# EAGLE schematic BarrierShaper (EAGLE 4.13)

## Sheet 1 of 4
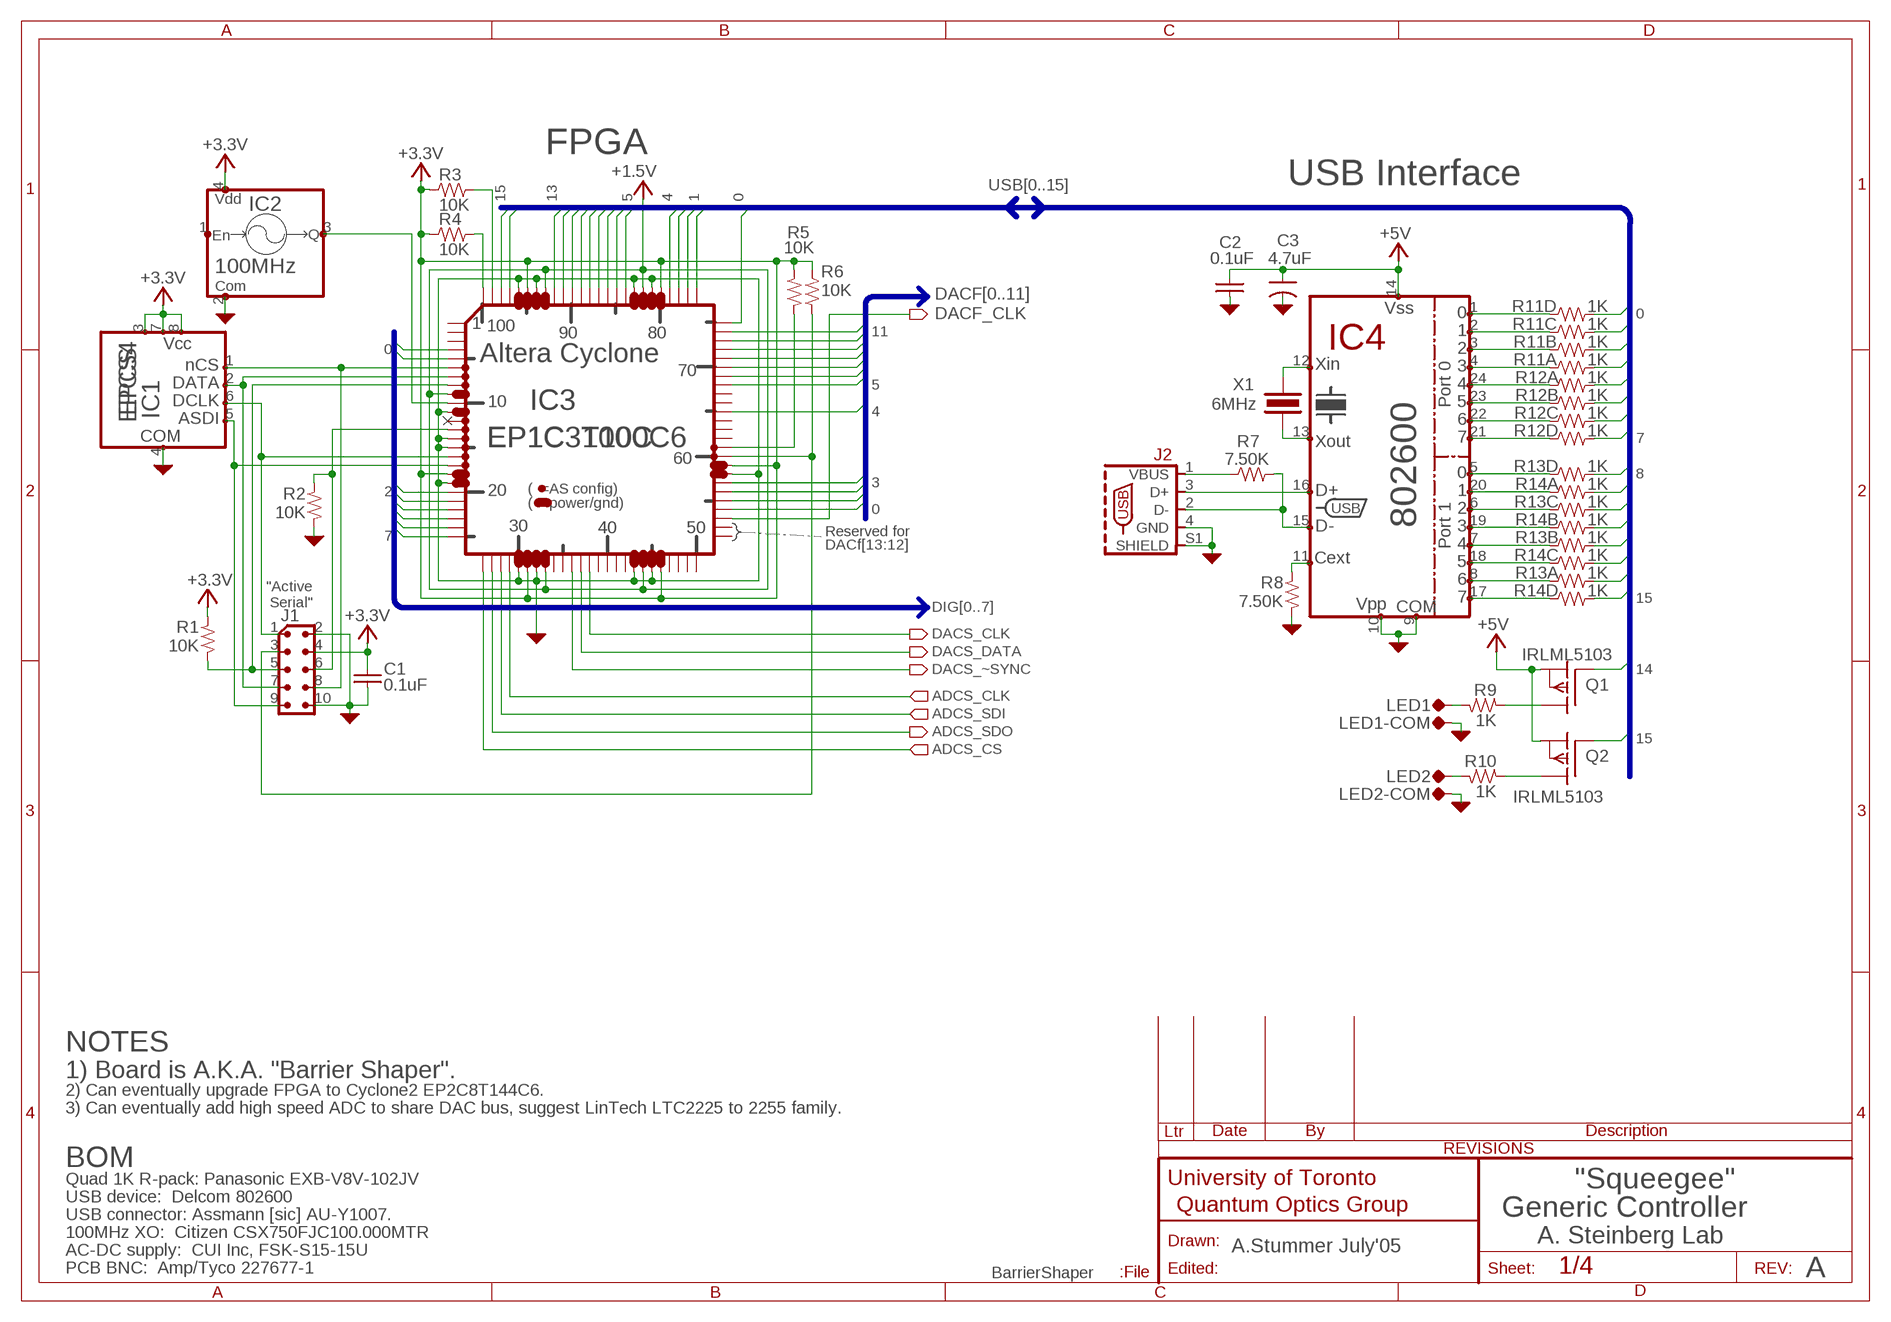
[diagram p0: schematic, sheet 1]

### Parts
C1  0.1uF  CAP-V-0805  [0805]
C2  0.1uF  CAP-V-0603  [0603]
C3  4.7uF  CAP-POL-3216  [EIA3216]
IC1  EPCS4  EPCS1-4(ALTERA_CONFIG)  [SOIC-8]
IC2  100MHz  CSX750(CITIZEN_OSC)  [CSX750(CITIZEN_OSC)]
IC3  EP1C3T100C6  ALTERA_EP1C--100--TQFP100  [TQFP-100]
IC4  802600(DELCOM-USB)-SOIC24  [SOIC-24-0.3]
J1  CONN-2X5-BLASTER  [CONN-2X5-BLASTER]
J2  AU-Y1007-USB-B  [CONN-USB_AU-Y1007]
LED1  TP-HOLE-0.042  [TP-HOLE]
LED1-COM  TP-HOLE-0.042  [TP-HOLE]
LED2  TP-HOLE-0.042  [TP-HOLE]
LED2-COM  TP-HOLE-0.042  [TP-HOLE]
Q1  IRLML5103  MOSFET-P-SOT23  [SOT23]
Q2  IRLML5103  MOSFET-P-SOT23  [SOT23]
R1  10K  R-V-0805  [0805]
R2  10K  R-V-0805  [0805]
R3  10K  R-H-0805  [0805]
R4  10K  R-H-0805  [0805]
R5  10K  R-V-0805  [0805]
R6  10K  R-V-0805  [0805]
R7  7.50K  R-H-0805  [0805]
R8  7.50K  R-V-0805  [0805]
R9  1K  R-H-0805  [0805]
R10  1K  R-H-0805  [0805]
R11  1K  R-4PAK-EXB-8V8  [PANASONIC_EXB-V8V(QUAD-R-PACK)]
R12  1K  R-4PAK-EXB-8V8  [PANASONIC_EXB-V8V(QUAD-R-PACK)]
R13  1K  R-4PAK-EXB-8V8  [PANASONIC_EXB-V8V(QUAD-R-PACK)]
R14  1K  R-4PAK-EXB-8V8  [PANASONIC_EXB-V8V(QUAD-R-PACK)]
X1  6MHz  XTAL/RESONATOR-P  [RESONATOR-P]

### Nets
+1.5V [Power]: IC3.9 IC3.33 IC3.44 IC3.82 IC3.93 ; also sheet 3
+3.3V [Power]: C1.2 IC1.3(VCC1) IC1.7(VCC2) IC1.8(VCC3) IC2.4(VDD) IC3.18 IC3.31 IC3.46 IC3.59 IC3.80 IC3.95 J1.4 R1.2 R3.1 R4.1 R5.2 R6.2 ; also sheet 2,3
+5V: C2.2 C3.+(POS) IC4.14(VCC) Q1.2(S) Q2.2(S) ; also sheet 2,3
ADCS_CLK: IC3.29 ; also sheet 2
ADCS_CS: IC3.26 ; also sheet 2
ADCS_SDI: IC3.28 ; also sheet 2
ADCS_SDO: IC3.27 ; also sheet 2
AGND: C1.1 C2.1 C3.-(NEG) IC1.4(COM) IC2.2(COM) IC3.11 IC3.14 IC3.15 IC3.19 IC3.30 IC3.32 IC3.43 IC3.45 IC3.58 IC3.81 IC3.83 IC3.94 IC3.96 IC4.9(COM) IC4.10(VPP) J1.2 J1.10 J2.4(GND) J2.S1(SHIELD) LED1-COM.P$1(TP) LED2-COM.P$1(TP) R2.1 R8.1 ; also sheet 2,3
DACF0: IC3.54 ; also sheet 2
DACF1: IC3.55 ; also sheet 2
DACF2: IC3.56 ; also sheet 2
DACF3: IC3.57 ; also sheet 2
DACF4: IC3.65 ; also sheet 2
DACF5: IC3.68 ; also sheet 2
DACF6: IC3.69 ; also sheet 2
DACF7: IC3.70 ; also sheet 2
DACF8: IC3.71 ; also sheet 2
DACF9: IC3.72 ; also sheet 2
DACF10: IC3.73 ; also sheet 2
DACF11: IC3.74 ; also sheet 2
DACF_CLK: IC3.53 ; also sheet 2
DACS_CLK: IC3.38 ; also sheet 2
DACS_DATA: IC3.37 ; also sheet 2
DACS_~SYNC: IC3.36 ; also sheet 2
DIG0: IC3.4 ; also sheet 2
DIG1: IC3.5 ; also sheet 2
DIG2: IC3.20 ; also sheet 2
DIG3: IC3.21 ; also sheet 2
DIG4: IC3.22 ; also sheet 2
DIG5: IC3.23 ; also sheet 2
DIG6: IC3.24 ; also sheet 2
DIG7: IC3.25 ; also sheet 2
N$1: IC1.1(NCS) IC3.6 J1.8
N$2: IC1.2(DATA) IC3.7 J1.7
N$3: IC1.6(DCLK) IC3.16 J1.1
N$4: IC1.5(ASDI) IC3.17 J1.9
N$5: IC3.60 J1.3 R6.1
N$6: IC3.8 J1.5 R1.1
N$7: IC3.13 J1.6 R2.2
N$8: IC3.61 R5.1
N$9: IC2.3(Q) IC3.10
N$10: IC3.100 R4.2
N$11: IC3.99 R3.2
N$62: IC4.8(P1.6) R13.1A
N$63: IC4.7(P1.4) R13.2A
N$64: IC4.17(P1.7) R14.4A
N$65: IC4.6(P1.2) R13.3A
N$66: IC4.19(P1.3) R14.2A
N$67: IC4.18(P1.5) R14.3A
N$68: IC4.20(P1.1) R14.1A
N$69: IC4.5(P1.0) R13.4A
N$70: IC4.15(D-) J2.2(D-) R7.2
N$71: IC4.16(D+) J2.3(D+)
N$72: IC4.13(XTL2) X1.1(X1)
N$73: IC4.12(XTL1) X1.2(X2)
N$74: Q1.3(D) R9.1
N$75: LED1.P$1(TP) R9.2
N$76: Q2.3(D) R10.1
N$77: LED2.P$1(TP) R10.2
N$78: IC4.11(CEXT) R8.2
N$79: IC4.4(P0.3) R11.1A
N$80: IC4.3(P0.2) R11.2A
N$81: IC4.21(P0.7) R12.4A
N$82: IC4.22(P0.6) R12.3A
N$83: IC4.23(P0.5) R12.2A
N$84: IC4.24(P0.4) R12.1A
N$85: IC4.2(P0.1) R11.3A
N$86: IC4.1(P0.0) R11.4A
N$104: J2.1(VBUS) R7.1
USB0: IC3.75 R11.4B
USB1: IC3.76 R11.3B
USB2: IC3.77 R11.2B
USB3: IC3.78 R11.1B
USB4: IC3.79 R12.1B
USB5: IC3.84 R12.2B
USB6: IC3.85 R12.3B
USB7: IC3.86 R12.4B
USB8: IC3.87 R13.4B
USB9: IC3.88 R14.1B
USB10: IC3.89 R13.3B
USB11: IC3.90 R14.2B
USB12: IC3.91 R13.2B
USB13: IC3.92 R14.3B
USB14: IC3.97 Q1.1(G) R13.1B
USB15: IC3.98 Q2.1(G) R14.4B
Unconnected: IC2.1(EN) IC3.1 IC3.2 IC3.3 IC3.12 IC3.34 IC3.35 IC3.39 IC3.40 IC3.41 IC3.42 IC3.47 IC3.48 IC3.49 IC3.50 IC3.51 IC3.52 IC3.62 IC3.63 IC3.64 IC3.66 IC3.67

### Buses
DACF[0..11]
USB[0..15]
DIG[0..7]

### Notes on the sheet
- FPGA
- USB Interface
- 15 | 13 | 5 | 4 | 1 | 0
- 0
- 11
- 0
- 5
- 4
- 7
- 8
- 3
- 2
- 0
- Reserved for
- 7
- DACf[13:12]
- "Active
- 15
- Serial"
- 14
- 15
- NOTES
- 1) Board is A.K.A. "Barrier Shaper".
- 2) Can eventually upgrade FPGA to Cyclone2 EP2C8T144C6.
- 3) Can eventually add high speed ADC to share DAC bus, suggest LinTech LTC2225 to 2255 family.
- BOM
- Quad 1K R-pack: Panasonic EXB-V8V-102JV | "Squeegee"
- USB device:  Delcom 802600
- USB connector: Assmann [sic] AU-Y1007. | Generic Controller
- 100MHz XO:  Citizen CSX750FJC100.000MTR
- A. Steinberg Lab
- AC-DC supply:  CUI Inc, FSK-S15-15U | A.Stummer July'05
- PCB BNC:  Amp/Tyco 227677-1 | A

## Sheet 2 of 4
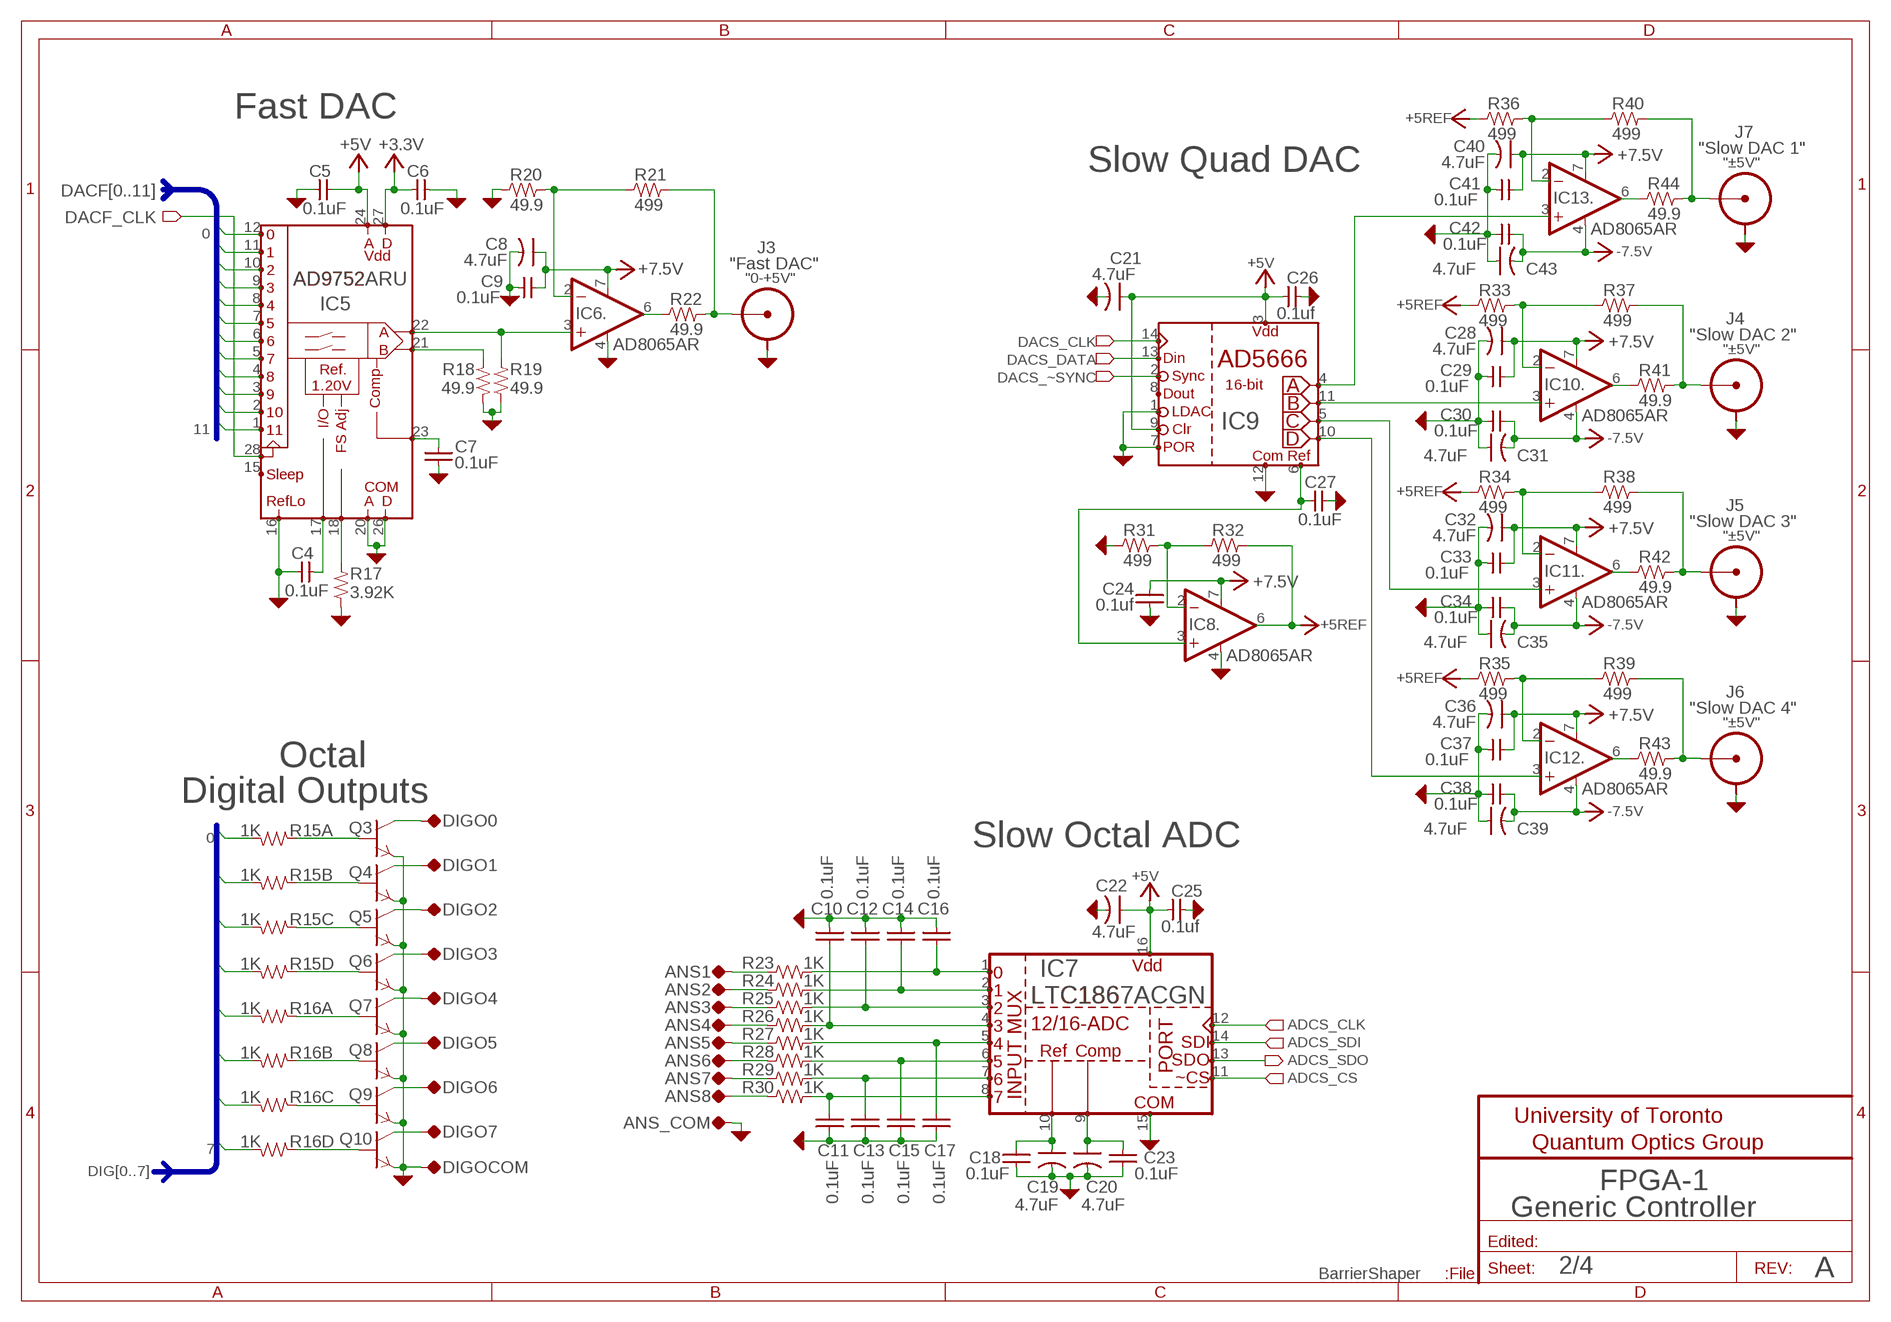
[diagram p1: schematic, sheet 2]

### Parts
ANS1  TP-0.042"  [TP-0.042]
ANS2  TP-0.042"  [TP-0.042]
ANS3  TP-0.042"  [TP-0.042]
ANS4  TP-0.042"  [TP-0.042]
ANS5  TP-0.042"  [TP-0.042]
ANS6  TP-0.042"  [TP-0.042]
ANS7  TP-0.042"  [TP-0.042]
ANS8  TP-0.042"  [TP-0.042]
ANS_COM  TP-0.042"  [TP-0.042]
C4  0.1uF  CAP-H-0805  [0805]
C5  0.1uF  CAP-H-0805  [0805]
C6  0.1uF  CAP-H-0805  [0805]
C7  0.1uF  CAP-V-0805  [0805]
C8  4.7uF  CAP-POL-3216  [EIA3216]
C9  0.1uF  CAP-H-0805  [0805]
C10  0.1uF  CAP-V-0805  [0805]
C11  0.1uF  CAP-V-0805  [0805]
C12  0.1uF  CAP-V-0805  [0805]
C13  0.1uF  CAP-V-0805  [0805]
C14  0.1uF  CAP-V-0805  [0805]
C15  0.1uF  CAP-V-0805  [0805]
C16  0.1uF  CAP-V-0805  [0805]
C17  0.1uF  CAP-V-0805  [0805]
C18  0.1uF  CAP-V-0603  [0603]
C19  4.7uF  CAP-POL-3216  [EIA3216]
C20  4.7uF  CAP-POL-3216  [EIA3216]
C21  4.7uF  CAP-POL-3216  [EIA3216]
C22  4.7uF  CAP-POL-3216  [EIA3216]
C23  0.1uF  CAP-V-0603  [0603]
C24  0.1uf  CAP-V-0603  [0603]
C25  0.1uf  CAP-H-0603  [0603]
C26  0.1uf  CAP-H-0603  [0603]
C27  0.1uF  CAP-H-0603  [0603]
C28  4.7uF  CAP-POL-3216  [EIA3216]
C29  0.1uF  CAP-H-0805  [0805]
C30  0.1uF  CAP-H-0805  [0805]
C31  4.7uF  CAP-POL-3216  [EIA3216]
C32  4.7uF  CAP-POL-3216  [EIA3216]
C33  0.1uF  CAP-H-0805  [0805]
C34  0.1uF  CAP-H-0805  [0805]
C35  4.7uF  CAP-POL-3216  [EIA3216]
C36  4.7uF  CAP-POL-3216  [EIA3216]
C37  0.1uF  CAP-H-0805  [0805]
C38  0.1uF  CAP-H-0805  [0805]
C39  4.7uF  CAP-POL-3216  [EIA3216]
C40  4.7uF  CAP-POL-3216  [EIA3216]
C41  0.1uF  CAP-H-0805  [0805]
C42  0.1uF  CAP-H-0805  [0805]
C43  4.7uF  CAP-POL-3216  [EIA3216]
DIGO0  TP-0.042"  [TP-0.042]
DIGO1  TP-0.042"  [TP-0.042]
DIGO2  TP-0.042"  [TP-0.042]
DIGO3  TP-0.042"  [TP-0.042]
DIGO4  TP-0.042"  [TP-0.042]
DIGO5  TP-0.042"  [TP-0.042]
DIGO6  TP-0.042"  [TP-0.042]
DIGO7  TP-0.042"  [TP-0.042]
DIGOCOM  TP-0.042"  [TP-0.042]
IC5  AD9752ARU  [TSSOP-28]
IC6  AD8065AR  OPAMP-SO8  [SOIC-8]
IC7  LTC1867ACGN  LTC1867(OCTAL12-16-ADC)  [SSOP-16]
IC8  AD8065AR  OPAMP-SO8  [SOIC-8]
IC9  AD5666(QUAD16-DAC)  [TSSOP-14]
IC10  AD8065AR  OPAMP-SO8  [SOIC-8]
IC11  AD8065AR  OPAMP-SO8  [SOIC-8]
IC12  AD8065AR  OPAMP-SO8  [SOIC-8]
IC13  AD8065AR  OPAMP-SO8  [SOIC-8]
J3  "Fast DAC"  CONN-BNCTYPE3HORIZ  [CONN-BNC-AMP-TYPE3HORIZ]
J4  "Slow DAC 2"  CONN-BNCTYPE3HORIZ  [CONN-BNC-AMP-TYPE3HORIZ]
J5  "Slow DAC 3"  CONN-BNCTYPE3HORIZ  [CONN-BNC-AMP-TYPE3HORIZ]
J6  "Slow DAC 4"  CONN-BNCTYPE3HORIZ  [CONN-BNC-AMP-TYPE3HORIZ]
J7  "Slow DAC 1"  CONN-BNCTYPE3HORIZ  [CONN-BNC-AMP-TYPE3HORIZ]
Q3  ZXT13N50DE6(ZETEX-NPN-SW-SOT223-6)  [SOT23-6MODIFIED]
Q4  ZXT13N50DE6(ZETEX-NPN-SW-SOT223-6)  [SOT23-6MODIFIED]
Q5  ZXT13N50DE6(ZETEX-NPN-SW-SOT223-6)  [SOT23-6MODIFIED]
Q6  ZXT13N50DE6(ZETEX-NPN-SW-SOT223-6)  [SOT23-6MODIFIED]
Q7  ZXT13N50DE6(ZETEX-NPN-SW-SOT223-6)  [SOT23-6MODIFIED]
Q8  ZXT13N50DE6(ZETEX-NPN-SW-SOT223-6)  [SOT23-6MODIFIED]
Q9  ZXT13N50DE6(ZETEX-NPN-SW-SOT223-6)  [SOT23-6MODIFIED]
Q10  ZXT13N50DE6(ZETEX-NPN-SW-SOT223-6)  [SOT23-6MODIFIED]
R15  1K  R-4PAK-EXB-8V8  [PANASONIC_EXB-V8V(QUAD-R-PACK)]
R16  1K  R-4PAK-EXB-8V8  [PANASONIC_EXB-V8V(QUAD-R-PACK)]
R17  3.92K  R-V-0805  [0805]
R18  49.9  R-V-0805  [0805]
R19  49.9  R-V-0805  [0805]
R20  49.9  R-H-0805  [0805]
R21  499  R-H-0805  [0805]
R22  49.9  R-H-0805  [0805]
R23  1K  R-H-0805  [0805]
R24  1K  R-H-0805  [0805]
R25  1K  R-H-0805  [0805]
R26  1K  R-H-0805  [0805]
R27  1K  R-H-0805  [0805]
R28  1K  R-H-0805  [0805]
R29  1K  R-H-0805  [0805]
R30  1K  R-H-0805  [0805]
R31  499  R-H-0805  [0805]
R32  499  R-H-0805  [0805]
R33  499  R-H-0805  [0805]
R34  499  R-H-0805  [0805]
R35  499  R-H-0805  [0805]
R36  499  R-H-0805  [0805]
R37  499  R-H-0805  [0805]
R38  499  R-H-0805  [0805]
R39  499  R-H-0805  [0805]
R40  499  R-H-0805  [0805]
R41  49.9  R-H-0805  [0805]
R42  49.9  R-H-0805  [0805]
R43  49.9  R-H-0805  [0805]
R44  49.9  R-H-0805  [0805]

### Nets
+3.3V [Power]: C6.1 IC5.27(DVDD) ; also sheet 1,3
+5REF: IC8.6(.:OUT) R32.2 R33.1 R34.1 R35.1 R36.1
+5V: C5.2 C21.+(POS) C22.+(POS) C25.1 C26.1 IC5.24(AVDD) IC7.16(VDD) IC9.3(VDD) IC9.9(~CLR) ; also sheet 1,3
+7.5V: C8.+(POS) C9.1 C24.2 C28.+(POS) C29.1 C32.+(POS) C33.1 C36.+(POS) C37.1 C40.+(POS) C41.1 IC6.7(V+) IC8.7(V+) IC10.7(V+) IC11.7(V+) IC12.7(V+) IC13.7(V+) ; also sheet 3
-7.5V: C30.1 C31.-(NEG) C34.1 C35.-(NEG) C38.1 C39.-(NEG) C42.1 C43.-(NEG) IC10.4(V-) IC11.4(V-) IC12.4(V-) IC13.4(V-) ; also sheet 3
ADCS_CLK: IC7.12(CLK) ; also sheet 1
ADCS_CS: IC7.11(~CS) ; also sheet 1
ADCS_SDI: IC7.14(SDI) ; also sheet 1
ADCS_SDO: IC7.13(SDO) ; also sheet 1
AGND: ANS_COM.TP C4.1 C5.1 C6.2 C7.1 C8.-(NEG) C9.2 C10.1 C11.1 C12.1 C13.1 C14.1 C15.1 C16.1 C17.1 C18.1 C19.-(NEG) C20.-(NEG) C21.-(NEG) C22.-(NEG) C23.1 C24.1 C25.2 C26.2 C27.2 C28.-(NEG) C29.2 C30.2 C31.+(POS) C32.-(NEG) C33.2 C34.2 C35.+(POS) C36.-(NEG) C37.2 C38.2 C39.+(POS) C40.-(NEG) C41.2 C42.2 C43.+(POS) DIGOCOM.TP IC5.16(REFLO) IC5.20(ACOM) IC5.26(DCOM) IC6.4(V-) IC7.15(COM) IC8.4(V-) IC9.1(~LDAC) IC9.7(POR) IC9.12(COM) J3.SHIELD J4.SHIELD J5.SHIELD J6.SHIELD J7.SHIELD Q3.4(E) Q4.4(E) Q5.4(E) Q6.4(E) Q7.4(E) Q8.4(E) Q9.4(E) Q10.4(E) R17.1 R18.1 R19.1 R20.1 R31.1 ; also sheet 1,3
DACF0: IC5.12 ; also sheet 1
DACF1: IC5.11 ; also sheet 1
DACF2: IC5.10 ; also sheet 1
DACF3: IC5.9 ; also sheet 1
DACF4: IC5.8 ; also sheet 1
DACF5: IC5.7 ; also sheet 1
DACF6: IC5.6 ; also sheet 1
DACF7: IC5.5 ; also sheet 1
DACF8: IC5.4 ; also sheet 1
DACF9: IC5.3 ; also sheet 1
DACF10: IC5.2 ; also sheet 1
DACF11: IC5.1 ; also sheet 1
DACF_CLK: IC5.28(CLK) ; also sheet 1
DACS_CLK: IC9.14(SCLK) ; also sheet 1
DACS_DATA: IC9.13(DIN) ; also sheet 1
DACS_~SYNC: IC9.2(~SYNC) ; also sheet 1
DIG0: R15.1B ; also sheet 1
DIG1: R15.2B ; also sheet 1
DIG2: R15.3B ; also sheet 1
DIG3: R15.4B ; also sheet 1
DIG4: R16.1B ; also sheet 1
DIG5: R16.2B ; also sheet 1
DIG6: R16.3B ; also sheet 1
DIG7: R16.4B ; also sheet 1
N$12: IC10.2(.:-IN) R33.2 R37.1
N$13: IC13.2(.:-IN) R36.2 R40.1
N$14: IC13.6(.:OUT) R44.1
N$15: J7.CONDUCTOR R40.2 R44.2
N$16: IC10.6(.:OUT) R41.1
N$17: C27.1 IC8.3(.:+IN) IC9.6(VREF)
N$18: J4.CONDUCTOR R37.2 R41.2
N$19: IC9.5(OUT-C) IC11.3(.:+IN)
N$20: DIGO6.TP Q9.1(C)
N$21: IC11.2(.:-IN) R34.2 R38.1
N$22: IC11.6(.:OUT) R42.1
N$23: J5.CONDUCTOR R38.2 R42.2
N$24: IC9.10(OUT-D) IC12.3(.:+IN)
N$25: IC12.2(.:-IN) R35.2 R39.1
N$26: IC12.6(.:OUT) R43.1
N$27: J6.CONDUCTOR R39.2 R43.2
N$28: C4.2 IC5.17(REF)
N$29: IC5.18(FSADJ) R17.2
N$30: IC5.21(IOUTB) R18.2
N$31: IC5.22(IOUTA) IC6.3(.:+IN) R19.2
N$32: C7.2 IC5.23(COMP)
N$33: IC6.2(.:-IN) R20.2 R21.1
N$34: IC6.6(.:OUT) R22.1
N$35: J3.CONDUCTOR R21.2 R22.2
N$36: IC9.11(OUT-B) IC10.3(.:+IN)
N$37: IC8.2(.:-IN) R31.2 R32.1
N$38: ANS1.TP R23.1
N$39: C18.2 C19.+(POS) IC7.10(VREF)
N$40: C20.+(POS) C23.2 IC7.9(COMP)
N$41: IC9.4(OUT-A) IC13.3(.:+IN)
N$42: C11.2 IC7.8 R30.2
N$43: C13.2 IC7.7 R29.2
N$44: C15.2 IC7.6 R28.2
N$45: C17.2 IC7.5 R27.2
N$46: C10.2 IC7.4 R26.2
N$47: C12.2 IC7.3 R25.2
N$48: C14.2 IC7.2 R24.2
N$49: C16.2 IC7.1 R23.2
N$50: ANS2.TP R24.1
N$51: ANS3.TP R25.1
N$52: ANS4.TP R26.1
N$53: ANS5.TP R27.1
N$54: ANS6.TP R28.1
N$55: ANS7.TP R29.1
N$56: ANS8.TP R30.1
N$57: DIGO7.TP Q10.1(C)
N$58: DIGO0.TP Q3.1(C)
N$59: DIGO1.TP Q4.1(C)
N$60: DIGO2.TP Q5.1(C)
N$61: DIGO3.TP Q6.1(C)
N$87: DIGO4.TP Q7.1(C)
N$88: DIGO5.TP Q8.1(C)
N$89: Q3.3(B) R15.1A
N$90: Q4.3(B) R15.2A
N$91: Q10.3(B) R16.4A
N$92: Q9.3(B) R16.3A
N$93: Q8.3(B) R16.2A
N$94: Q7.3(B) R16.1A
N$95: Q6.3(B) R15.4A
N$96: Q5.3(B) R15.3A
Unconnected: IC5.15(SLEEP) IC9.8(SDO)

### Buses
USB[0..15]
DACF[0..11]
DIG[0..7]

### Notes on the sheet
- Fast DAC
- "±5V"
- Slow Quad DAC
- 0
- "0-+5V"
- "±5V"
- 11
- "±5V"
- "±5V"
- Octal
- Digital Outputs
- 0
- Slow Octal ADC
- 7
- FPGA-1
- Generic Controller
- A

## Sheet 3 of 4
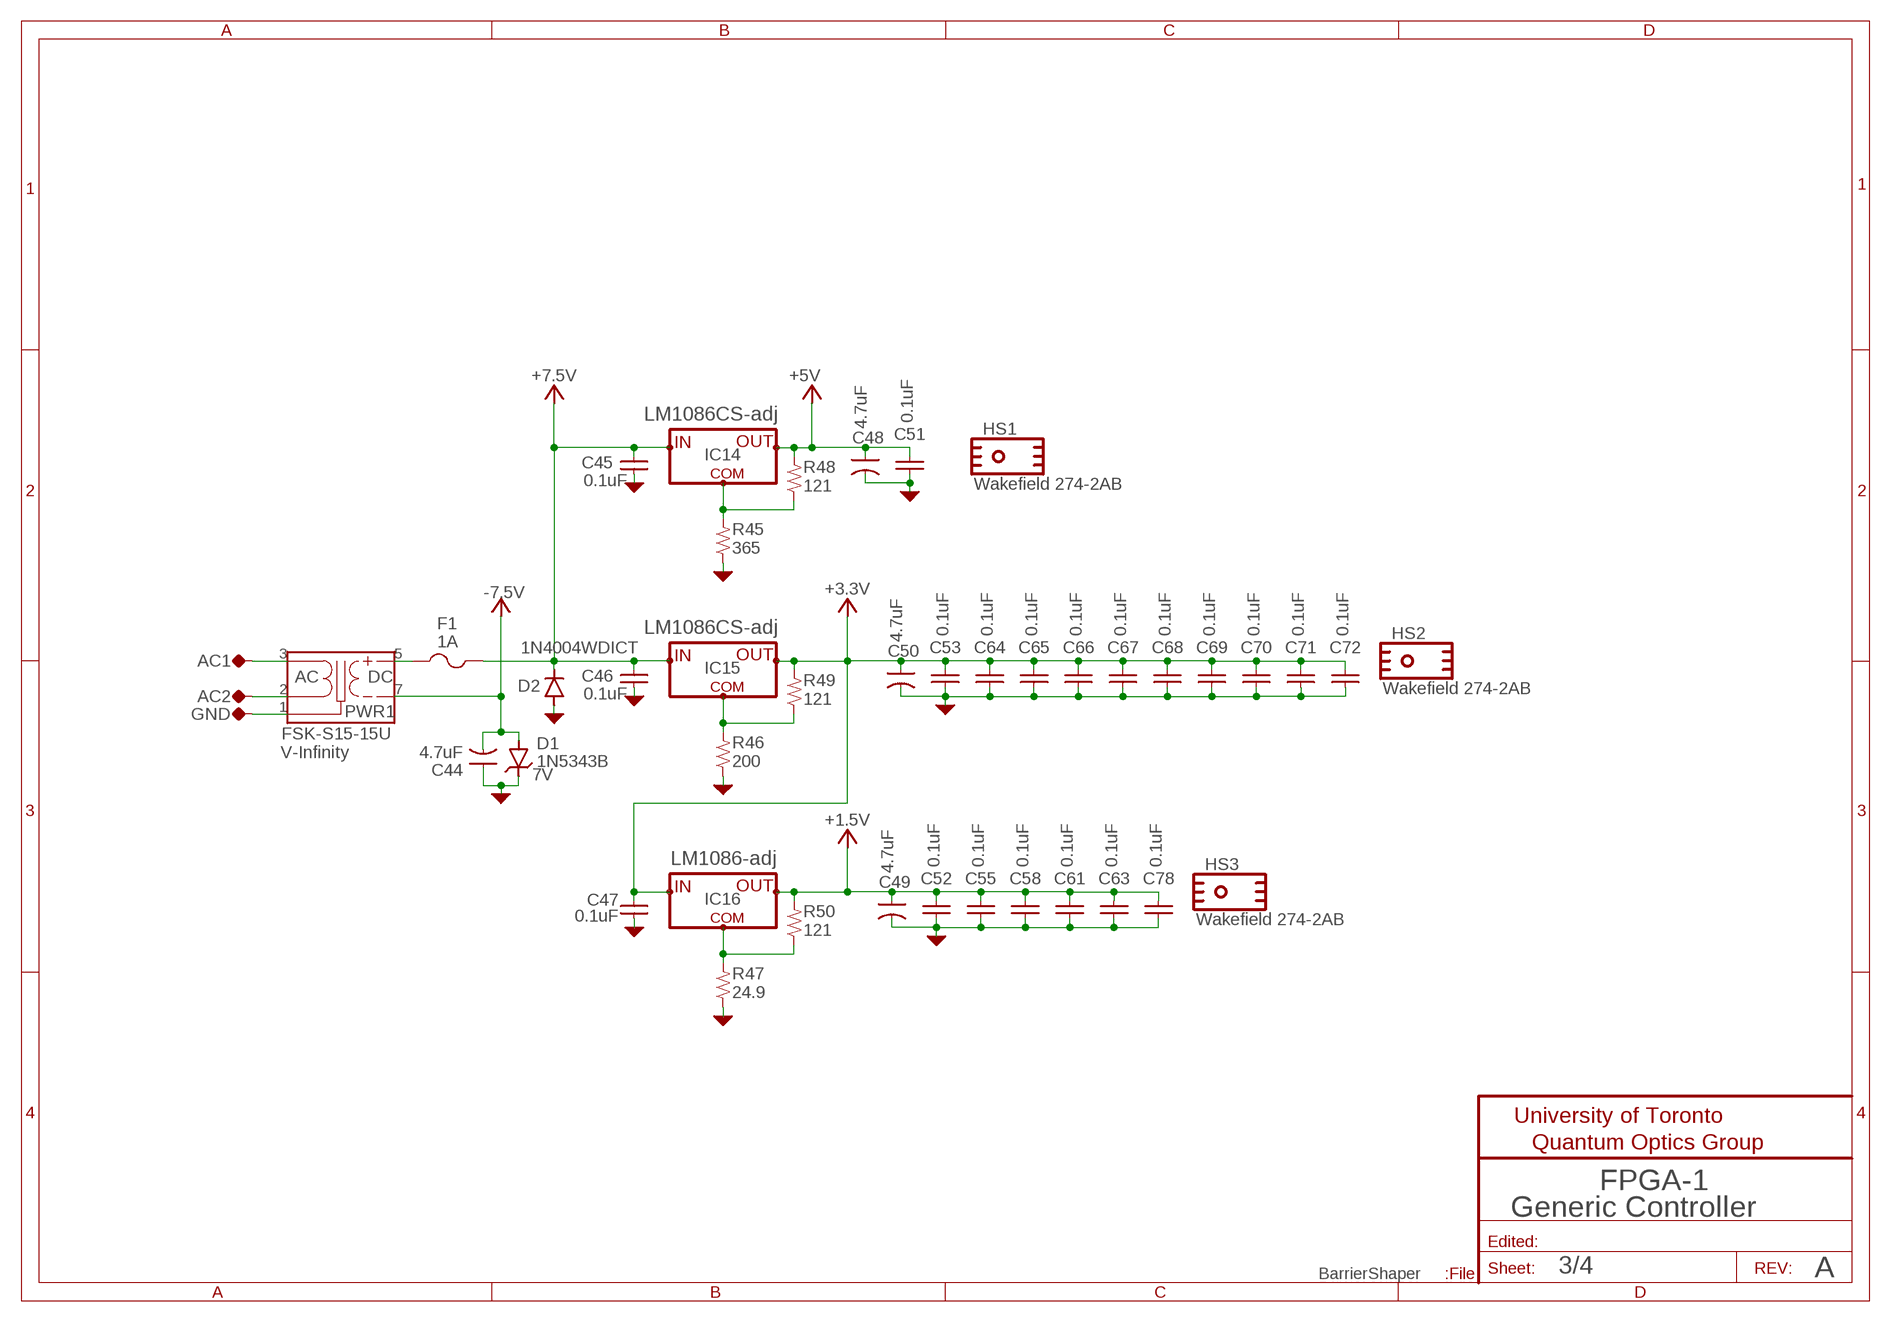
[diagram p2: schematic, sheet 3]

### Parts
AC1  TP-0.125"  [TP-0.125]
AC2  TP-0.125"  [TP-0.125]
C44  4.7uF  CAP-POL-3216  [EIA3216]
C45  0.1uF  CAP-V-0603  [0603]
C46  0.1uF  CAP-V-0603  [0603]
C47  0.1uF  CAP-V-0603  [0603]
C48  4.7uF  CAP-POL-3216  [EIA3216]
C49  4.7uF  CAP-POL-3216  [EIA3216]
C50  4.7uF  CAP-POL-3216  [EIA3216]
C51  0.1uF  CAP-V-0603  [0603]
C52  0.1uF  CAP-V-0603  [0603]
C53  0.1uF  CAP-V-0603  [0603]
C55  0.1uF  CAP-V-0603  [0603]
C58  0.1uF  CAP-V-0603  [0603]
C61  0.1uF  CAP-V-0603  [0603]
C63  0.1uF  CAP-V-0603  [0603]
C64  0.1uF  CAP-V-0603  [0603]
C65  0.1uF  CAP-V-0603  [0603]
C66  0.1uF  CAP-V-0603  [0603]
C67  0.1uF  CAP-V-0603  [0603]
C68  0.1uF  CAP-V-0603  [0603]
C69  0.1uF  CAP-V-0603  [0603]
C70  0.1uF  CAP-V-0603  [0603]
C71  0.1uF  CAP-V-0603  [0603]
C72  0.1uF  CAP-V-0603  [0603]
C78  0.1uF  CAP-V-0603  [0603]
D1  1N5343B  ZENER-THROUGH-0.4"  [PASSIVE_0.4"]
D2  1N4004WDICT  [EIA-B(SMB)]
F1  1A  FUSE5X20-2  [FUSE_LITTLEFUSE05200002Z]
GND  TP-0.125"  [TP-0.125]
HS1  Wakefield 274-2AB  HEATSINK-274AB  [HEATSINK-3]
HS2  Wakefield 274-2AB  HEATSINK-274AB  [HEATSINK-3]
HS3  Wakefield 274-2AB  HEATSINK-274AB  [HEATSINK-3]
IC14  LM1086CS-adj  LM1086-TO263  [TO263]
IC15  LM1086CS-adj  LM1086-TO263  [TO263]
IC16  LM1086-adj  LM1086-TO263  [TO263]
PWR1  FSK-S15-15U  CUI_FSK15  [CUI_FSK15]
R45  365  R-V-0805  [0805]
R46  200  R-V-0805  [0805]
R47  24.9  R-V-0805  [0805]
R48  121  R-V-0805  [0805]
R49  121  R-V-0805  [0805]
R50  121  R-V-0805  [0805]

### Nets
+1.5V [Power]: C49.+(POS) C52.2 C55.2 C58.2 C61.2 C63.2 C78.2 IC16.2(OUT) R50.2 ; also sheet 1
+3.3V [Power]: C47.2 C50.+(POS) C53.2 C64.2 C65.2 C66.2 C67.2 C68.2 C69.2 C70.2 C71.2 C72.2 IC15.2(OUT) IC16.3(VI) R49.2 ; also sheet 1,2
+5V: C48.+(POS) C51.2 IC14.2(OUT) R48.2 ; also sheet 1,2
+7.5V: C45.2 C46.2 D2.K+(C) F1.2(2A) IC14.3(VI) IC15.3(VI) ; also sheet 2
-7.5V: C44.-(NEG) D1.1(A) PWR1.7(V-) ; also sheet 2
AGND: C44.+(POS) C45.1 C46.1 C47.1 C48.-(NEG) C49.-(NEG) C50.-(NEG) C51.1 C52.1 C53.1 C55.1 C58.1 C61.1 C63.1 C64.1 C65.1 C66.1 C67.1 C68.1 C69.1 C70.1 C71.1 C72.1 C78.1 D1.2(C) D2.A-(A) R45.1 R46.1 R47.1 ; also sheet 1,2
N$97: IC15.1(COM) R46.2 R49.1
N$98: IC16.1(COM) R47.2 R50.1
N$99 [Power]: F1.1(1A) PWR1.5(V+)
N$100 [AC_Line]: AC1.TP PWR1.3(AC-H)
N$101 [AC_Line]: AC2.TP PWR1.2(AC-L)
N$102 [AC_Line]: GND.TP PWR1.1(FG)
N$103: IC14.1(COM) R45.2 R48.1

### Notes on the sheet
- V-Infinity
- 7V
- FPGA-1
- Generic Controller
- A

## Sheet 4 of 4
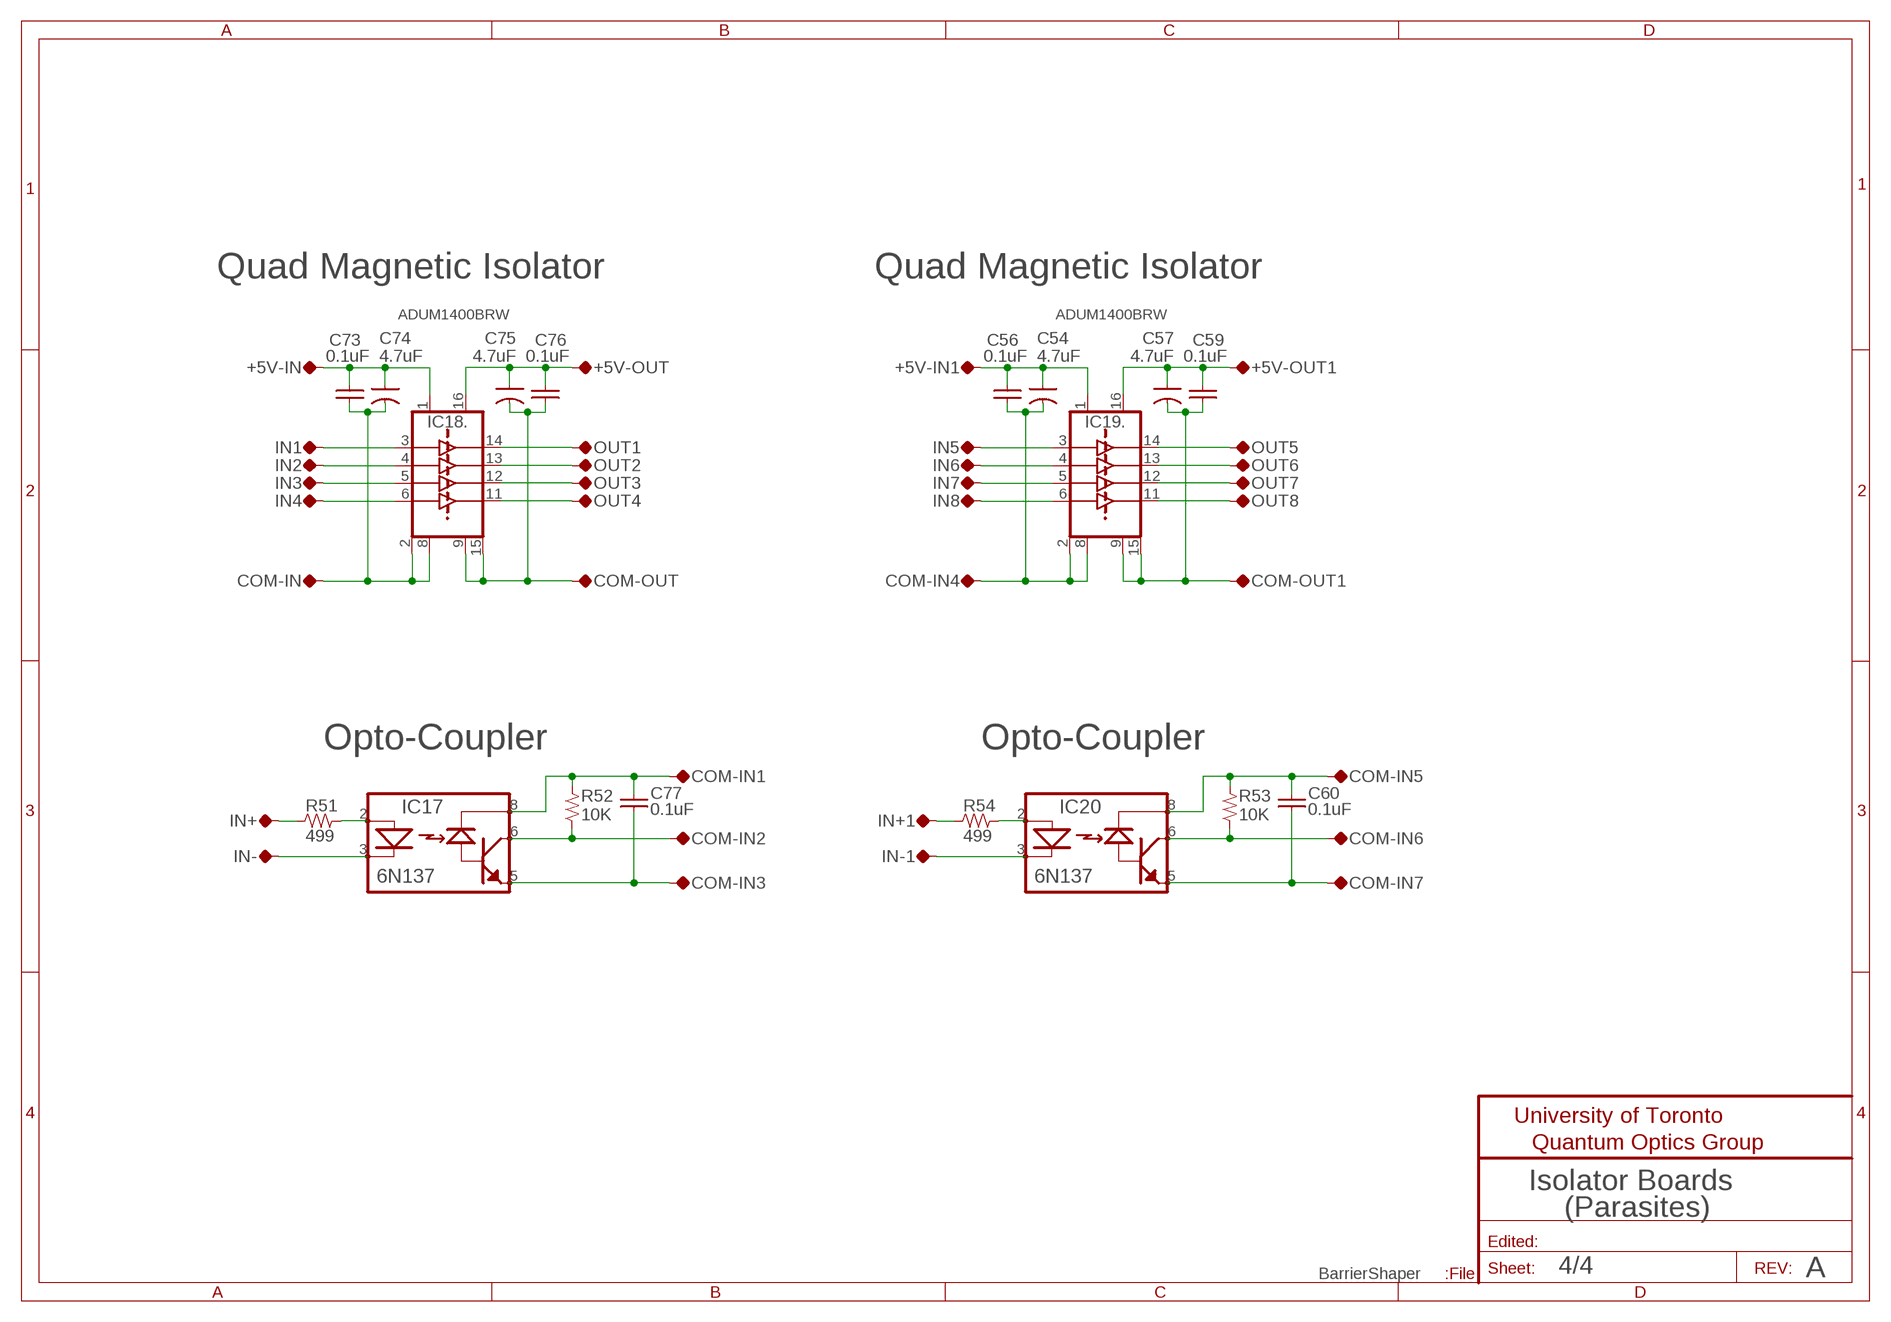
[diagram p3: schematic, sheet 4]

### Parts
+5V-IN  TP-0.042"  [TP-0.042]
+5V-IN1  TP-0.042"  [TP-0.042]
+5V-OUT  TP-0.042"  [TP-0.042]
+5V-OUT1  TP-0.042"  [TP-0.042]
C54  4.7uF  CAP-POL-3216  [EIA3216]
C56  0.1uF  CAP-V-0805  [0805]
C57  4.7uF  CAP-POL-3216  [EIA3216]
C59  0.1uF  CAP-V-0805  [0805]
C60  0.1uF  CAP-V-0805  [0805]
C73  0.1uF  CAP-V-0805  [0805]
C74  4.7uF  CAP-POL-3216  [EIA3216]
C75  4.7uF  CAP-POL-3216  [EIA3216]
C76  0.1uF  CAP-V-0805  [0805]
C77  0.1uF  CAP-V-0805  [0805]
COM-IN  TP-0.042"  [TP-0.042]
COM-IN1  TP-0.042"  [TP-0.042]
COM-IN2  TP-0.042"  [TP-0.042]
COM-IN3  TP-0.042"  [TP-0.042]
COM-IN4  TP-0.042"  [TP-0.042]
COM-IN5  TP-0.042"  [TP-0.042]
COM-IN6  TP-0.042"  [TP-0.042]
COM-IN7  TP-0.042"  [TP-0.042]
COM-OUT  TP-0.042"  [TP-0.042]
COM-OUT1  TP-0.042"  [TP-0.042]
IC17  6N137  6N136(OPTOCOUPLER)  [DIL08]
IC18  ADUM1400BRW  ISOLATOR,QUADTTLSOIC-16W  [SOIC-16W]
IC19  ADUM1400BRW  ISOLATOR,QUADTTLSOIC-16W  [SOIC-16W]
IC20  6N137  6N136(OPTOCOUPLER)  [DIL08]
IN1  TP-0.042"  [TP-0.042]
IN2  TP-0.042"  [TP-0.042]
IN3  TP-0.042"  [TP-0.042]
IN4  TP-0.042"  [TP-0.042]
IN5  TP-0.042"  [TP-0.042]
IN6  TP-0.042"  [TP-0.042]
IN7  TP-0.042"  [TP-0.042]
IN8  TP-0.042"  [TP-0.042]
IN+  TP-0.042"  [TP-0.042]
IN+1  TP-0.042"  [TP-0.042]
IN-  TP-0.042"  [TP-0.042]
IN-1  TP-0.042"  [TP-0.042]
OUT1  TP-0.042"  [TP-0.042]
OUT2  TP-0.042"  [TP-0.042]
OUT3  TP-0.042"  [TP-0.042]
OUT4  TP-0.042"  [TP-0.042]
OUT5  TP-0.042"  [TP-0.042]
OUT6  TP-0.042"  [TP-0.042]
OUT7  TP-0.042"  [TP-0.042]
OUT8  TP-0.042"  [TP-0.042]
R51  499  R-H-0805  [0805]
R52  10K  R-V-0805  [0805]
R53  10K  R-V-0805  [0805]
R54  499  R-H-0805  [0805]

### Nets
N$105: IC18.3(IN) IN1.TP
N$106: IC18.4(IN) IN2.TP
N$107: IC18.5(IN) IN3.TP
N$108: IC18.6(IN) IN4.TP
N$109: IC19.3(IN) IN5.TP
N$110: +5V-IN.TP C73.2 C74.+(POS) IC18.1(.:VDDIN)
N$111: C73.1 C74.-(NEG) COM-IN.TP IC18.2(.:COM1IN) IC18.8(.:COM2IN)
N$112: IC18.14(Q) OUT1.TP
N$113: IC18.13(Q) OUT2.TP
N$114: IC18.12(Q) OUT3.TP
N$115: IC18.11(Q) OUT4.TP
N$116: +5V-OUT.TP C75.+(POS) C76.2 IC18.16(.:VDDOUT)
N$117: C75.-(NEG) C76.1 COM-OUT.TP IC18.9(.:COM1OUT) IC18.15(.:COM2OUT)
N$118: IN+.TP R51.1
N$119: IC17.3(CATHODE) IN-.TP
N$120: IC17.2(ANODE) R51.2
N$121: C77.2 COM-IN1.TP IC17.8(VDD) R52.2
N$122: COM-IN2.TP IC17.6(OUT) R52.1
N$123: C77.1 COM-IN3.TP IC17.5(COM)
N$124: IC19.4(IN) IN6.TP
N$125: IC19.5(IN) IN7.TP
N$126: IC19.6(IN) IN8.TP
N$127: +5V-IN1.TP C54.+(POS) C56.2 IC19.1(.:VDDIN)
N$128: C54.-(NEG) C56.1 COM-IN4.TP IC19.2(.:COM1IN) IC19.8(.:COM2IN)
N$129: IC19.14(Q) OUT5.TP
N$130: IC19.13(Q) OUT6.TP
N$131: IC19.12(Q) OUT7.TP
N$132: IC19.11(Q) OUT8.TP
N$133: +5V-OUT1.TP C57.+(POS) C59.2 IC19.16(.:VDDOUT)
N$134: C57.-(NEG) C59.1 COM-OUT1.TP IC19.9(.:COM1OUT) IC19.15(.:COM2OUT)
N$135: IN+1.TP R54.1
N$136: IC20.3(CATHODE) IN-1.TP
N$137: IC20.2(ANODE) R54.2
N$138: C60.2 COM-IN5.TP IC20.8(VDD) R53.2
N$139: COM-IN6.TP IC20.6(OUT) R53.1
N$140: C60.1 COM-IN7.TP IC20.5(COM)

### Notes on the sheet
- Quad Magnetic Isolator | Quad Magnetic Isolator
- Opto-Coupler | Opto-Coupler
- Isolator Boards
- (Parasites)
- A

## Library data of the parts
+5V-IN +5V-IN1 +5V-OUT +5V-OUT1 AC1 AC2 ANS1-ANS8 ANS_COM COM-IN COM-IN1-COM-IN7 COM-OUT COM-OUT1 DIGO0 DIGO1-DIGO7 DIGOCOM GND IN1-IN8 IN+ IN+1 IN- IN-1 LED1 LED1-COM LED2 LED2-COM OUT1-OUT8 = QuantumOptics:TP: Testpoint, test point on schematic, on PCB either SMT pad, small hole or loop style TP.
C1 C2 C7 C10-C18 C23 C24 C45-C47 C51-C53 C55 C56 C58-C61 C63-C73 C76-C78 = QuantumOptics:CAP-V-: Cap, SMT and Through-hole, 0402 and up.
C3 C8 C19-C22 C28 C31 C32 C35 C36 C39 C40 C43 C44 C48-C50 C54 C57 C74 C75 = QuantumOptics:CAP-POL-: Capacitor, Polarized, SMT 0805 and up, probably tantalum.
C4-C6 C9 C25-C27 C29 C30 C33 C34 C37 C38 C41 C42 = QuantumOptics:CAP-H-: Cap, SMT and Through-hole, 0402 and up.
D1 = QuantumOptics:ZENER: Zener
D2 = QuantumOptics:1N4004: DIODE, general purpose rectifier, 1 A
F1 = QuantumOptics:FUSE: Fuse
HS1-HS3 = QuantumOptics:HEATSINK: Heatsink, generic, placeholder so part gets added to BOM. Must give it a value.
IC1 = QuantumOptics:EPCS1-4(ALTERA_CONFIG): EPCS1 or EPCS4, Altera, FPGA serial configuration device.
IC2 = QuantumOptics:CSX750(CITIZEN_OSC): CSX750 Oscillators, Citizen, +3.3V or +5V, 1MHZ to 133MHz. http://rocky.digikey.com/WebLib/Citizen/Web%20Data/CSX750FB.pdf
IC3 = QuantumOptics:ALTERA_EP1C--100-: FPGA, Altera Cyclone, EP1Cxx100x, such as EP1C3T100C6.
IC4 = QuantumOptics:802600(DELCOM-USB): 802600 USB Peripheral, Delcom, 16-bit USB to parallel interface, quick and dirty USB 1.1 peripheral solution.
IC5 = QuantumOptics:AD9752: AD9752, Analog Device, 12-bit DAC, 145MHz, parallel. http://www.analog.com/UploadedFiles/Data_Sheets/70523322AD9752_0.pdf
IC6 IC8 IC10-IC13 = QuantumOptics:OPAMP: Op Amp, generic, pick the right package.
IC7 = QuantumOptics:LTC1867(OCTAL12-16-ADC): LTC1863/7 Linear Technology, octal 12- or 16-bit ADC, serial, uni/bipolar, SE/diff, http://www.linear.com/pc/downloadDocument.do?navId=H0,C1,C1155,C1001,C1158,P2497,D2141
IC9 = QuantumOptics:AD5666(QUAD16-DAC): AD5666aruz-2, Analog Devices, quad serial 16-bit DAC, 14-TSSOP, http://www.analog.com/UploadedFiles/Data_Sheets/354265261AD5666_prb.pdf
IC14-IC16 = QuantumOptics:LM1086-: LM1086-xxx, National Semiconductor, LDO, adjustable or fixed. http://cache.national.com/ds/LM/LM1086.pdf
IC17 IC20 = QuantumOptics:6N136(OPTOCOUPLER): 6N136 optocoupler, Fairchild et al, 1Mbps CTR=27%typ, http://www.fairchildsemi.com/ds/6N/6N136.pdf, Can drop-in 6N137 with 10Mbps logic - http://www.fairchildsemi.com/ds/6N/6N137.pdf
IC18 IC19 = QuantumOptics:ISOLATOR,QUADTTL: Quad Isolator Analog Devices ADUM1400xxx (alternate NVE's IL715), http://www.analog.com/UploadedFiles/Data_Sheets/1013172531ADuM1400_1_2_c.pdf
J1 = QuantumOptics:CONN-2X5-BLASTER: Connector, 2 rows of 5 for ByteBlaster, USBBlaster or MasterBlaster, on 0.1" grid, pins numbering zig-zags top-left to bottom-right.
J2 = QuantumOptics:AU-Y1007: USB Device side Connector, Assman [sic], PCB. Square USB-B type connector for load side.
J3-J7 = QuantumOptics:CONN-BNC: BNC connector
PWR1 = QuantumOptics:CUI_FSK15: FSK15 Power Supply, from CUI Inc., 15W, through-hole. Metric dimensions now on 0.025" grid. Very big for its power: 70mm x 45 x 20. http://rocky.digikey.com/WebLib/CUI%20Inc/Web%20data/FSK15%20Series.pdf
Q1 Q2 = QuantumOptics:MOSFET-P: MOSFET, P-channel, generic, in SOT-23 package. Warning! Check pinout! e.g. IR IRLML5103CT-ND (30V, 0.6?), http://www.irf.com/product-info/datasheets/data/irlml5103.pdf.
Q3-Q10 = QuantumOptics:ZXT13N50DE6(ZETEX-NPN-SW-SOT223-6): ZXT13N50DE6, Zetex, NPN switching BJT, SOT-23-6, 50V, 4A, 0.036Ohm, http://www.zetex.com/3.0/pdf/ZXT13N50DE6.pdf
R1 R2 R5 R6 R8 R17-R19 R45-R50 R52 R53 = QuantumOptics:R-V-*: Resistor, SMT & Through-Hole, vertical symbol
R3 R4 R7 R9 R10 R20-R44 R51 R54 = QuantumOptics:R-H-*: Resistor, SMT & Through-Hole, horizontal symbol
R11-R16 = QuantumOptics:R-4PAK: Quad Resistor Pack
X1 = QuantumOptics:XTAL/RESONATOR: Crystal or Reonator. Besure to verify package, especially SMT pads sizes and locations.

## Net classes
0 default: width 0.203 mm, drill 0.203 mm, clearance 0.508 mm
2 AC_Line: width 0.203 mm, drill 1.27 mm, clearance 0.711 mm
3 Power: width 0.305 mm, drill 0.203 mm, clearance 0.711 mm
